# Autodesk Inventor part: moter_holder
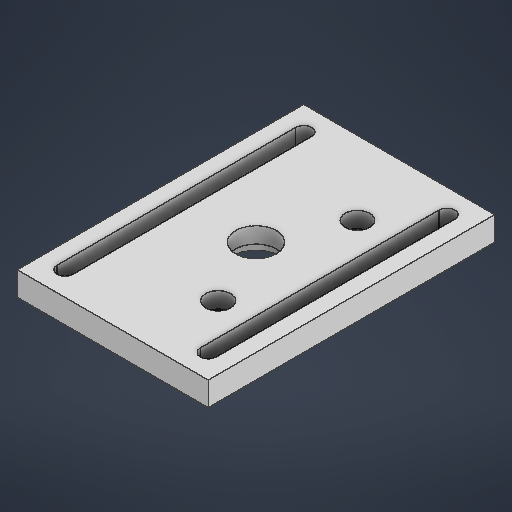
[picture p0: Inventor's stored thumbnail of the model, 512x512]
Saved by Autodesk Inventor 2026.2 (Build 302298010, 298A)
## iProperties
Created: 2026-05
Part Number: moter_holder
Material: 일반
Document SubType Name: Modeling
Designer: work
Density: 1 g/cm^3
Appearance: 기본값
Author: work
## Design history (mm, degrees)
sketch "스케치1" dims "d9" = 20
  geometry: L1 (0, 17.5)-(0, -17.5); L2 (8, 0)-(0, 0); L3 (8, 30)-(8, -30); L4 (26, 30)-(-10, 30); L5 (-10, 30)-(-10, -30); L6 (-10, -30)-(26, -30); L7 (26, -30)-(26, 30); L8 (26, 30)-(26, -30); L9 (24, 30)-(24, -30); L10 (28, -30)-(28, 30); L11 (-10, 30)-(-10, -30); L12 (-12, 30)-(-12, -30); L13 (-8, -30)-(-8, 30); L14 (-2, -34)-(-10, -34); L15 (-10, -34)-(-10, 34); L16 (-10, 34)-(-2, 34); L17 (-2, 34)-(-2, -34); L18 (-16, 36)-(32, 36); L19 (32, 36)-(32, -36); L20 (32, -36)-(-16, -36); L21 (-16, -36)-(-16, 36); L22 (-16, 36)-(32, -36); L23 (32, 36)-(-16, -36); C1 r 2.7 at (8, 0); C2 r 2 at (0, 17.5); C3 r 2 at (0, -17.5); A1 r 2 centre (26, 30) between (28, 30) and (24, 30); A2 r 2 centre (26, -30) between (24, -30) and (28, -30); A3 r 2 centre (-10, 30) between (-8, 30) and (-12, 30); A4 r 2 centre (-10, -30) between (-12, -30) and (-8, -30); 5 further points
  constraints: 50 end point, 11 midpoint, 9 parallel, 8 point on circle, 8 tangent, 7 centre point, 4 horizontal, 3 coincident, 3 perpendicular, 2 collinear, 1 horizontal alignment, 1 vertical, 2 other
  dimensions: "d0" = 5.4 diameter of C1; "d1" = 8 distance of L2.start L2.end; "d2" = 35 distance of L1.start L1.end; "d3" = 4 diameter of C2; "d4" = 4 diameter of C3; "d5" = 60 distance of L3.start L3.end; "d6" = 36 distance between parallel lines of L5 L7; "d7" = 4 diameter of A2; "d8" = 4 diameter of A4; "d10" = 4 distance between parallel lines of L4 L16; "d11" = 6 distance between parallel lines of L19 L8; "d12" = 6 distance between parallel lines of L20 L6
extrude "돌출1" new body sketch "스케치1" distance "d13" = 6; taper "d14" = 0 deg
sketch "스케치2"
  geometry: L1 (16, 36)-(-32, 36) reference; L2 (-32, 36)-(-32, -36) reference; L3 (-32, -36)-(16, -36) reference; L4 (16, -36)-(16, 36) reference; L5 (8, -30)-(8, 30) reference; L6 (12, 30)-(12, -30) reference; L7 (-28, -30)-(-28, 30) reference; L8 (-24, 30)-(-24, -30) reference; C1 r 2.7 at (-8, 0) reference; C2 r 2 at (0, -17.5) reference; C3 r 2 at (0, 17.5) reference; C4 r 3.15 at (0, -17.5); C5 r 3.1 at (0, 17.5); C6 r 5.1 at (-8, 0); A1 r 2 centre (10, -30) between (8, -30) and (12, -30) reference; A2 r 2 centre (10, 30) between (12, 30) and (8, 30) reference; A3 r 2 centre (-26, -30) between (-28, -30) and (-24, -30) reference; A4 r 2 centre (-26, 30) between (-24, 30) and (-28, 30) reference; 1 further point
  constraints: 3 centre point, 3 coincident
  dimensions: "d15" = 6.3 diameter of C4; "d16" = 6.2 diameter of C5; "d22" = 10.2 diameter of C6
extrude "돌출2" cut sketch "스케치2" distance "d17" = 4; taper "d18" = 0 deg
sketch "스케치3"
  geometry: L1 (16, -36)-(-32, -36) reference; L2 (16, 36)-(16, -36) reference; L3 (-32, 36)-(16, 36) reference; L4 (-32, -36)-(-32, 36) reference; L5 (12, -30)-(12, 30) reference; L6 (8, 30)-(8, -30) reference; L7 (-24, -30)-(-24, 30) reference; L8 (-28, 30)-(-28, -30) reference; C1 r 2.7 at (-8, 0) reference; C2 r 2 at (0, 17.5) reference; C3 r 2 at (0, -17.5) reference; C4 r 6 at (-8, 0); A1 r 2 centre (10, 30) between (12, 30) and (8, 30) reference; A2 r 2 centre (10, -30) between (8, -30) and (12, -30) reference; A3 r 2 centre (-26, 30) between (-24, 30) and (-28, 30) reference; A4 r 2 centre (-26, -30) between (-28, -30) and (-24, -30) reference; 1 further point
  constraints: 1 centre point, 1 coincident
  dimensions: "d23" = 12 diameter of C4
extrude "돌출3" cut sketch "스케치3" distance "d24" = 2; taper "d25" = 0 deg
node "솔리드1"
node "투영된 루프1"
node "투영된 루프2"
